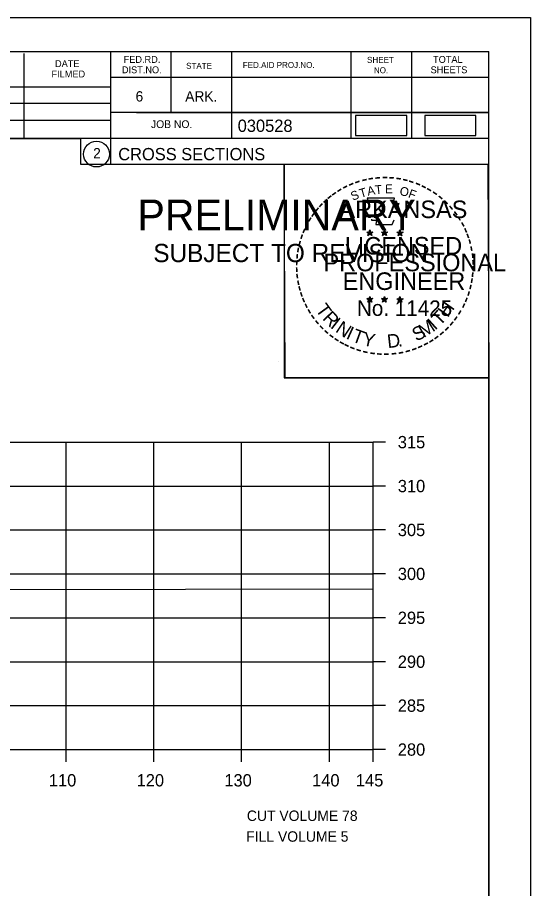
# Model space of a CAD drawing. Extents: x 1370843 to 1371177, y 380307 to 382654.
# Drawn here: x 1371118.2 to 1371176.6, y 380421.6 to 380520.8 of the extents above; entities that cross this region are included whole.
import ezdxf

# ---------------------------------------------------------------- set-up
doc = ezdxf.new("R2010")
doc.units = 0
for name, color, linetype in [('R_Axis', 7, 'Continuous'), ('R_Axis Annot', 7, 'Continuous'), ('R_Border', 7, 'Continuous'), ('R_Border Notes', 7, 'Continuous'), ('R_Border PE', 7, 'Continuous'), ('R_Border Prem', 7, 'Continuous'), ('R_Draft', 7, 'Continuous'), ('R_Exist Surface', 7, 'Continuous'), ('R_Grid', 7, 'Continuous'), ('R_No Plot', 7, 'Continuous')]:
    doc.layers.add(name, color=color, linetype=linetype)

msp = doc.modelspace()

# ---------------------------------------------------------------- linework, layer by layer
at = {"layer": 'R_Axis'}
for p, q in [((1371158.709, 380437.448), (1371158.709, 380472.448)), ((1371160.109, 380472.448), (1371158.709, 380472.448)), ((1371160.109, 380467.448), (1371158.709, 380467.448)), ((1371160.109, 380462.448), (1371158.709, 380462.448)), ((1371160.109, 380457.448), (1371158.709, 380457.448)), ((1371160.109, 380452.448), (1371158.709, 380452.448)), ((1371160.109, 380447.448), (1371158.709, 380447.448)), ((1371160.109, 380442.448), (1371158.709, 380442.448)), ((1370868.709, 380437.448), (1371158.709, 380437.448)), ((1371123.709, 380436.048), (1371123.709, 380437.448)), ((1371133.709, 380436.048), (1371133.709, 380437.448)), ((1371143.709, 380436.048), (1371143.709, 380437.448)), ((1371153.709, 380436.048), (1371153.709, 380437.448)), ((1371158.709, 380436.048), (1371158.709, 380437.448)), ((1371160.109, 380437.448), (1371158.709, 380437.448))]:
    msp.add_line(p, q, dxfattribs=at)
at = {"layer": 'R_Border'}
for p, q in [((1370855.709, 380516.908), (1371171.889, 380516.908)), ((1371118.929, 380507.028), (1371118.929, 380516.708)), ((1371128.789, 380516.908), (1371128.789, 380504.108)), ((1371135.629, 380516.908), (1371135.629, 380509.968)), ((1371142.569, 380516.908), (1371142.569, 380507.028)), ((1371156.149, 380516.908), (1371156.149, 380507.028)), ((1371163.089, 380516.908), (1371163.089, 380507.028)), ((1371171.889, 380311.448), (1371171.889, 380516.908)), ((1371171.889, 380513.968), (1371128.789, 380513.968)), ((1371171.889, 380513.988), (1371171.889, 380513.988)), ((1371089.629, 380512.888), (1371128.789, 380512.888)), ((1371089.629, 380511.028), (1371128.789, 380511.028)), ((1371171.889, 380509.968), (1371128.789, 380509.968)), ((1371131.749, 380509.968), (1371171.889, 380509.968)), ((1371089.629, 380509.088), (1371128.789, 380509.088)), ((1371171.889, 380507.028), (1371089.629, 380507.028)), ((1371128.789, 380504.108), (1371171.889, 380504.108))]:
    msp.add_line(p, q, dxfattribs=at)
msp.add_circle((1371127.176, 380505.244), 1.467, dxfattribs=at)
at = {"layer": 'R_Border PE'}
for p, q in [((1371157.974, 380496.363), (1371158.323, 380496.252)), ((1371157.974, 380496.363), (1371158.227, 380496.318)), ((1371157.974, 380496.363), (1371158.211, 380496.241)), ((1371158.107, 380495.955), (1371158.323, 380496.252)), ((1371158.107, 380495.955), (1371158.233, 380496.199)), ((1371158.107, 380495.955), (1371158.321, 380496.172)), ((1371158.323, 380496.617), (1371158.282, 380496.365)), ((1371158.536, 380495.955), (1371158.321, 380496.169)), ((1371158.323, 380496.252), (1371158.323, 380496.617)), ((1371158.323, 380496.617), (1371158.372, 380496.367)), ((1371158.67, 380496.363), (1371158.323, 380496.252)), ((1371158.536, 380495.955), (1371158.323, 380496.252)), ((1371158.67, 380496.363), (1371158.384, 380496.314)), ((1371158.536, 380495.955), (1371158.399, 380496.246)), ((1371158.67, 380496.363), (1371158.466, 380496.261)), ((1371159.644, 380496.363), (1371159.993, 380496.252)), ((1371159.644, 380496.363), (1371159.897, 380496.318)), ((1371159.644, 380496.363), (1371159.881, 380496.241)), ((1371159.777, 380495.955), (1371159.993, 380496.252)), ((1371159.777, 380495.955), (1371159.903, 380496.199)), ((1371159.777, 380495.955), (1371159.991, 380496.172)), ((1371159.993, 380496.617), (1371159.952, 380496.365)), ((1371160.206, 380495.955), (1371159.991, 380496.169)), ((1371159.993, 380496.252), (1371159.993, 380496.617)), ((1371159.993, 380496.617), (1371160.042, 380496.367)), ((1371160.34, 380496.363), (1371159.993, 380496.252)), ((1371160.206, 380495.955), (1371159.993, 380496.252)), ((1371160.34, 380496.363), (1371160.054, 380496.314)), ((1371160.206, 380495.955), (1371160.069, 380496.246)), ((1371160.34, 380496.363), (1371160.136, 380496.261)), ((1371161.408, 380496.351), (1371161.757, 380496.24)), ((1371161.408, 380496.351), (1371161.661, 380496.306)), ((1371161.408, 380496.351), (1371161.645, 380496.229)), ((1371161.541, 380495.943), (1371161.757, 380496.24)), ((1371161.541, 380495.943), (1371161.667, 380496.187)), ((1371161.541, 380495.943), (1371161.755, 380496.16)), ((1371161.757, 380496.605), (1371161.716, 380496.353)), ((1371161.97, 380495.943), (1371161.755, 380496.157)), ((1371161.757, 380496.24), (1371161.757, 380496.605)), ((1371161.757, 380496.605), (1371161.806, 380496.355)), ((1371162.104, 380496.351), (1371161.757, 380496.24)), ((1371161.97, 380495.943), (1371161.757, 380496.24)), ((1371162.104, 380496.351), (1371161.818, 380496.302)), ((1371161.97, 380495.943), (1371161.833, 380496.234)), ((1371162.104, 380496.351), (1371161.9, 380496.249)), ((1371157.97, 380488.79), (1371158.319, 380488.679)), ((1371157.97, 380488.79), (1371158.223, 380488.745)), ((1371157.97, 380488.79), (1371158.207, 380488.668)), ((1371158.319, 380489.044), (1371158.278, 380488.792)), ((1371158.319, 380488.679), (1371158.319, 380489.044)), ((1371158.319, 380489.044), (1371158.368, 380488.794)), ((1371158.666, 380488.79), (1371158.319, 380488.679)), ((1371158.666, 380488.79), (1371158.38, 380488.741)), ((1371158.666, 380488.79), (1371158.462, 380488.688)), ((1371159.639, 380488.79), (1371159.988, 380488.679)), ((1371159.639, 380488.79), (1371159.892, 380488.745)), ((1371159.639, 380488.79), (1371159.876, 380488.668)), ((1371159.988, 380489.044), (1371159.947, 380488.792)), ((1371159.988, 380488.679), (1371159.988, 380489.044)), ((1371159.988, 380489.044), (1371160.037, 380488.794)), ((1371160.335, 380488.79), (1371159.988, 380488.679)), ((1371160.335, 380488.79), (1371160.049, 380488.741)), ((1371160.335, 380488.79), (1371160.131, 380488.688)), ((1371161.406, 380488.78), (1371161.755, 380488.669)), ((1371161.406, 380488.78), (1371161.659, 380488.735)), ((1371161.406, 380488.78), (1371161.643, 380488.658)), ((1371161.755, 380489.034), (1371161.714, 380488.782)), ((1371161.755, 380488.669), (1371161.755, 380489.034)), ((1371161.755, 380489.034), (1371161.804, 380488.784)), ((1371162.102, 380488.78), (1371161.755, 380488.669)), ((1371162.102, 380488.78), (1371161.816, 380488.731)), ((1371162.102, 380488.78), (1371161.898, 380488.678)), ((1371158.103, 380488.382), (1371158.319, 380488.679)), ((1371158.103, 380488.382), (1371158.229, 380488.626)), ((1371158.103, 380488.382), (1371158.317, 380488.599)), ((1371158.532, 380488.382), (1371158.317, 380488.596)), ((1371158.532, 380488.382), (1371158.319, 380488.679)), ((1371158.532, 380488.382), (1371158.395, 380488.673)), ((1371159.772, 380488.382), (1371159.988, 380488.679)), ((1371159.772, 380488.382), (1371159.898, 380488.626)), ((1371159.772, 380488.382), (1371159.986, 380488.599)), ((1371160.201, 380488.382), (1371159.986, 380488.596)), ((1371160.201, 380488.382), (1371159.988, 380488.679)), ((1371160.201, 380488.382), (1371160.064, 380488.673)), ((1371161.539, 380488.372), (1371161.755, 380488.669)), ((1371161.539, 380488.372), (1371161.665, 380488.616)), ((1371161.539, 380488.372), (1371161.753, 380488.589)), ((1371161.968, 380488.372), (1371161.753, 380488.586)), ((1371161.968, 380488.372), (1371161.755, 380488.669)), ((1371161.968, 380488.372), (1371161.831, 380488.663))]:
    msp.add_line(p, q, dxfattribs=at)
for points in [[(1371158.015, 380500.241), (1371158.284, 380499.414)], [(1371161.526, 380499.319), (1371161.668, 380499.603), (1371160.983, 380499.579), (1371161.131, 380500.241), (1371158.015, 380500.241)], [(1371158.507, 380497.818), (1371158.507, 380497.731), (1371159.07, 380497.712), (1371159.016, 380497.239), (1371160.886, 380497.239), (1371161.087, 380497.775)], [(1371158.323, 380496.617), (1371158.536, 380495.955), (1371157.974, 380496.363), (1371158.67, 380496.363), (1371158.107, 380495.955), (1371158.323, 380496.617)], [(1371159.993, 380496.617), (1371160.206, 380495.955), (1371159.644, 380496.363), (1371160.34, 380496.363), (1371159.777, 380495.955), (1371159.993, 380496.617)], [(1371161.757, 380496.605), (1371161.97, 380495.943), (1371161.408, 380496.351), (1371162.104, 380496.351), (1371161.541, 380495.943), (1371161.757, 380496.605)], [(1371158.319, 380489.044), (1371158.532, 380488.382), (1371157.97, 380488.79), (1371158.666, 380488.79), (1371158.103, 380488.382), (1371158.319, 380489.044)], [(1371159.988, 380489.044), (1371160.201, 380488.382), (1371159.639, 380488.79), (1371160.335, 380488.79), (1371159.772, 380488.382), (1371159.988, 380489.044)], [(1371161.755, 380489.034), (1371161.968, 380488.372), (1371161.406, 380488.78), (1371162.102, 380488.78), (1371161.539, 380488.372), (1371161.755, 380489.034)]]:
    msp.add_lwpolyline(points, dxfattribs=at)
for centre, radius in [((1371158.322, 380496.251), 0.172), ((1371158.322, 380496.251), 0.145), ((1371158.322, 380496.251), 0.116), ((1371158.322, 380496.251), 0.0991), ((1371158.322, 380496.251), 0.0747), ((1371158.322, 380496.251), 0.0495), ((1371158.322, 380496.251), 0.0296), ((1371159.992, 380496.251), 0.172), ((1371159.992, 380496.251), 0.145), ((1371159.992, 380496.251), 0.116), ((1371159.992, 380496.251), 0.0991), ((1371159.992, 380496.251), 0.0747), ((1371159.992, 380496.251), 0.0495), ((1371159.992, 380496.251), 0.0296), ((1371161.756, 380496.239), 0.172), ((1371161.756, 380496.239), 0.145), ((1371161.756, 380496.239), 0.116), ((1371161.756, 380496.239), 0.0991), ((1371161.756, 380496.239), 0.0747), ((1371161.756, 380496.239), 0.0495), ((1371161.756, 380496.239), 0.0296), ((1371158.318, 380488.678), 0.172), ((1371158.318, 380488.678), 0.145), ((1371158.318, 380488.678), 0.116), ((1371158.318, 380488.678), 0.0991), ((1371158.318, 380488.678), 0.0747), ((1371158.318, 380488.678), 0.0495), ((1371159.987, 380488.678), 0.172), ((1371159.987, 380488.678), 0.145), ((1371159.987, 380488.678), 0.116), ((1371159.987, 380488.678), 0.0991), ((1371159.987, 380488.678), 0.0747), ((1371159.987, 380488.678), 0.0495), ((1371161.754, 380488.668), 0.172), ((1371161.754, 380488.668), 0.145), ((1371161.754, 380488.668), 0.116), ((1371161.754, 380488.668), 0.0991), ((1371161.754, 380488.668), 0.0747), ((1371158.318, 380488.678), 0.0296), ((1371159.987, 380488.678), 0.0296), ((1371161.754, 380488.668), 0.0495), ((1371161.754, 380488.668), 0.0296)]:
    msp.add_circle(centre, radius, dxfattribs=at)
at = {"layer": 'R_Draft'}
for points in [[(1371156.702, 380507.343), (1371162.536, 380507.343), (1371162.536, 380509.653), (1371156.702, 380509.653)], [(1371164.572, 380507.343), (1371170.406, 380507.343), (1371170.406, 380509.653), (1371164.572, 380509.653)]]:
    msp.add_lwpolyline(points, close=True, dxfattribs=at)
at = {"layer": 'R_Exist Surface'}
msp.add_line((1371109.054, 380455.675), (1371158.709, 380455.742), dxfattribs=at)
at = {"layer": 'R_Grid'}
for p, q in [((1370868.709, 380472.448), (1371158.709, 380472.448)), ((1371123.709, 380437.448), (1371123.709, 380472.448)), ((1371133.709, 380437.448), (1371133.709, 380472.448)), ((1371143.709, 380437.448), (1371143.709, 380472.448)), ((1371153.709, 380437.448), (1371153.709, 380472.448)), ((1371158.709, 380437.448), (1371158.709, 380472.448)), ((1370868.709, 380467.448), (1371158.709, 380467.448)), ((1370868.709, 380462.448), (1371158.709, 380462.448)), ((1370868.709, 380457.448), (1371158.709, 380457.448)), ((1370868.709, 380452.448), (1371158.709, 380452.448)), ((1370868.709, 380447.448), (1371158.709, 380447.448)), ((1370868.709, 380442.448), (1371158.709, 380442.448)), ((1370868.709, 380437.448), (1371158.709, 380437.448))]:
    msp.add_line(p, q, dxfattribs=at)
at = {"layer": 'R_No Plot'}
for p, q in [((1370843.308, 380520.803), (1371176.642, 380520.803)), ((1371147.923, 380481.653), (1371147.923, 380481.653))]:
    msp.add_line(p, q, dxfattribs=at)
for points in [[(1370843.302, 380520.803), (1371176.642, 380520.803), (1371176.642, 380307.465), (1370843.302, 380307.465)], [(1371089.629, 380516.908), (1371089.629, 380507.028), (1371125.361, 380507.028), (1371125.361, 380504.108), (1371148.561, 380504.108), (1371148.561, 380479.776), (1371171.889, 380479.776), (1371171.889, 380311.448), (1370855.709, 380311.448), (1370855.709, 380516.908)], [(1371148.561, 380504.108), (1371171.768, 380504.108), (1371171.889, 380479.776), (1371148.681, 380479.776)]]:
    msp.add_lwpolyline(points, close=True, dxfattribs=at)

# ---------------------------------------------------------------- texts
at = {"layer": 'R_Axis Annot'}
for s, p in [('315', (1371161.509, 380471.748)), ('310', (1371161.509, 380466.748)), ('305', (1371161.509, 380461.748)), ('300', (1371161.509, 380456.748)), ('295', (1371161.509, 380451.748)), ('290', (1371161.509, 380446.748)), ('285', (1371161.509, 380441.748)), ('280', (1371161.509, 380436.748)), ('110', (1371121.748, 380433.248)), ('120', (1371131.748, 380433.248)), ('130', (1371141.748, 380433.248)), ('140', (1371151.748, 380433.248)), ('145', (1371156.735, 380433.248))]:
    msp.add_text(s, height=1.4, dxfattribs=at).set_placement(p)
at = {"layer": 'R_Border'}
for s, height, p in [('DATE', 0.7819, (1371122.449, 380515.148)), ('FED.RD.', 0.7819, (1371130.269, 380515.628)), ('STATE', 0.684, (1371137.389, 380514.948)), ('FED.AID PROJ.NO.', 0.684, (1371143.849, 380515.048)), ('SHEET', 0.684, (1371158.009, 380515.628)), ('TOTAL', 0.7819, (1371165.529, 380515.628)), ('FILMED', 0.7819, (1371122.049, 380513.968)), ('DIST.NO.', 0.7819, (1371130.069, 380514.448)), ('NO.', 0.684, (1371158.789, 380514.448)), ('SHEETS', 0.7819, (1371165.249, 380514.448)), ('6', 1.172, (1371131.629, 380511.228)), ('ARK.', 1.1723, (1371137.289, 380511.228)), ('JOB NO.', 0.8792, (1371133.389, 380508.208)), ('030528', 1.4, (1371143.265, 380507.768)), ('2', 1.172, (1371126.793, 380504.757)), ('CROSS SECTIONS', 1.4, (1371129.653, 380504.538))]:
    msp.add_text(s, height=height, rotation=360, dxfattribs=at).set_placement(p)
at = {"layer": 'R_Border Notes'}
for s, p in [('CUT VOLUME 78', (1371144.31, 380429.317)), ('FILL VOLUME 5', (1371144.235, 380426.954))]:
    msp.add_text(s, height=1.18747, dxfattribs=at).set_placement(p)
at = {"layer": 'R_Border PE'}
for s, height, rotation, p in [('-', 1.6, 5.89682, (1371158.92, 380501.881)), ('-', 1.6, 0.18623, (1371159.692, 380501.953)), ('-', 1.6, 357.74304, (1371160.415, 380501.94)), ('-', 1.6, 28.79182, (1371155.496, 380500.782)), ('-', 1.6, 24.30721, (1371156.129, 380501.099)), ('-', 1.6, 19.17608, (1371156.763, 380501.368)), ('-', 1.6, 13.63015, (1371157.513, 380501.609)), ('-', 1.6, 10.21935, (1371158.191, 380501.771)), ('T', 1, 6.02276, (1371158.959, 380500.667)), ('E', 1, 0.83234, (1371160.064, 380500.777)), ('-', 1.6, 352.16172, (1371161.159, 380501.884)), ('-', 1.6, 347.20489, (1371161.878, 380501.77)), ('-', 1.6, 342.3362, (1371162.513, 380501.615)), ('-', 1.6, 337.85509, (1371163.248, 380501.392)), ('-', 1.6, 334.12109, (1371163.879, 380501.121)), ('-', 1.6, 36.23174, (1371154.321, 380500.017)), ('-', 1.6, 34.06357, (1371154.899, 380500.412)), ('S', 1, 21.59401, (1371156.37, 380499.919)), ('T', 1, 16.4036, (1371157.284, 380500.25)), ('A', 1, 11.21318, (1371158.11, 380500.501)), ('O', 1, 350.4515, (1371161.668, 380500.567)), ('F', 1, 340.07066, (1371162.622, 380500.339)), ('-', 1.6, 329.64089, (1371164.458, 380500.838)), ('-', 1.6, 325.86266, (1371165.101, 380500.477)), ('-', 1.6, 48.42305, (1371152.964, 380498.744)), ('-', 1.6, 42.96224, (1371153.412, 380499.222)), ('-', 1.6, 38.95066, (1371153.845, 380499.639)), ('ARKANSAS', 2, 360, (1371154.868, 380497.953)), ('-', 1.6, 320.52971, (1371165.711, 380500.051)), ('-', 1.6, 315.57859, (1371166.31, 380499.563)), ('-', 1.6, 50.61417, (1371152.561, 380498.258)), ('-', 1.6, 309.87973, (1371166.879, 380499.013)), ('-', 1.6, 306.65218, (1371167.404, 380498.411)), ('-', 1.6, 58.07063, (1371151.823, 380497.164)), ('-', 1.6, 54.23247, (1371152.148, 380497.691)), ('-', 1.4, 303.67529, (1371167.89, 380497.843)), ('-', 1.6, 67.77427, (1371151.251, 380495.939)), ('-', 1.6, 62.87135, (1371151.51, 380496.55)), ('-', 1.6, 299.66835, (1371168.209, 380497.236)), ('-', 1.6, 294.66279, (1371168.533, 380496.624)), ('-', 1.6, 72.39447, (1371151.032, 380495.309)), ('LICENSED', 2, 360, (1371155.465, 380493.804)), ('DWB', 0.01, 360, (1371158.31, 380496.247)), ('DWB', 0.01, 360, (1371159.98, 380496.247)), ('DWB', 0.01, 360, (1371161.744, 380496.236)), ('-', 1.6, 290.57283, (1371168.79, 380496.047)), ('-', 1.6, 75.46096, (1371150.835, 380494.595)), ('-', 1.6, 285.12326, (1371169.024, 380495.467)), ('-', 1.6, 280.54934, (1371169.224, 380494.725)), ('-', 1.6, 85.18634, (1371150.627, 380493.191)), ('-', 1.6, 81.20126, (1371150.703, 380493.882)), ('PROFESSIONAL', 2, 360, (1371153.042, 380491.9)), ('-', 1.6, 276.59616, (1371169.386, 380493.957)), ('-', 1.6, 89.06224, (1371150.602, 380492.49)), ('-', 1.6, 274.33011, (1371169.446, 380493.235)), ('-', 1.6, 94.19588, (1371150.637, 380491.765)), ('ENGINEER', 2, 360, (1371155.229, 380489.775)), ('-', 1.6, 263.5172, (1371169.461, 380491.937)), ('-', 1.6, 269.94067, (1371169.48, 380492.603)), ('-', 1.6, 98.94793, (1371150.709, 380491.098)), ('-', 1.6, 101.71495, (1371150.844, 380490.365)), ('-', 1.6, 260.99529, (1371169.39, 380491.283)), ('-', 1.6, 105.45785, (1371151.006, 380489.77)), ('-', 1.6, 255.7626, (1371169.28, 380490.605)), ('-', 1.6, 109.08742, (1371151.221, 380489.139)), ('-', 1.6, 114.06432, (1371151.475, 380488.543)), ('-', 1.6, 247.88866, (1371168.876, 380489.212)), ('-', 1.6, 252.86809, (1371169.099, 380489.885)), ('-', 1.6, 115.72885, (1371151.78, 380487.925)), ('T', 1.54, 306.04056, (1371152.078, 380487.517)), ('No. 11425', 1.757, 360, (1371156.856, 380486.824)), ('DWB', 0.01, 360, (1371158.306, 380488.674)), ('DWB', 0.01, 360, (1371159.975, 380488.674)), ('DWB', 0.01, 360, (1371161.742, 380488.664)), ('H', 1.54, 54.60883, (1371167.199, 380486.553)), ('-', 1.6, 244.61971, (1371168.614, 380488.583)), ('-', 1.6, 120.44712, (1371152.137, 380487.339)), ('-', 1.6, 125.89344, (1371152.54, 380486.778)), ('R', 1.54, 314.00497, (1371152.841, 380486.47)), ('T', 1.54, 46.64442, (1371166.309, 380485.61)), ('-', 1.6, 233.84524, (1371167.818, 380487.178)), ('-', 1.6, 239.07125, (1371168.22, 380487.831)), ('-', 1.6, 130.71812, (1371153.002, 380486.226)), ('-', 1.6, 134.22381, (1371153.519, 380485.681)), ('I', 1.54, 321.96938, (1371153.741, 380485.538)), ('N', 1.54, 326.50021, (1371154.309, 380485.066)), ('M', 1.54, 32.65632, (1371164.463, 380484.285)), ('I', 1.54, 42.11359, (1371165.747, 380485.132)), ('-', 1.6, 231.25377, (1371167.388, 380486.612)), ('-', 1.6, 138.93382, (1371154.044, 380485.217)), ('I', 1.54, 335.36034, (1371155.517, 380484.28)), ('T', 1.54, 339.89117, (1371156.178, 380483.953)), ('Y', 1.54, 347.85558, (1371157.395, 380483.507)), ('D', 1.54, 6.39691, (1371160.38, 380483.149)), ('S', 1.54, 26.9312, (1371163.624, 380483.879)), ('-', 1.6, 221.08509, (1371166.387, 380485.539)), ('-', 1.6, 225.76533, (1371166.909, 380486.048)), ('-', 1.6, 144.64634, (1371154.6, 380484.811)), ('-', 1.6, 148.08978, (1371155.161, 380484.44)), ('-', 1.6, 151.57039, (1371155.74, 380484.115)), ('-', 1.6, 207.35684, (1371164.746, 380484.334)), ('-', 1.6, 212.24909, (1371165.304, 380484.68)), ('-', 1.6, 215.73633, (1371165.838, 380485.067)), ('-', 1.6, 154.60019, (1371156.262, 380483.868)), ('-', 1.6, 158.56121, (1371156.886, 380483.614)), ('-', 1.6, 162.79826, (1371157.573, 380483.401)), ('-', 1.6, 167.55551, (1371158.288, 380483.237)), ('.', 1.54, 13.76417, (1371161.572, 380483.276)), ('-', 1.6, 195.47429, (1371162.826, 380483.5)), ('-', 1.6, 200.71842, (1371163.503, 380483.742)), ('-', 1.6, 204.25161, (1371164.122, 380484.015)), ('-', 1.6, 173.11546, (1371159.06, 380483.127)), ('-', 1.6, 176.51827, (1371159.808, 380483.074)), ('-', 1.6, 181.59176, (1371160.552, 380483.093)), ('-', 1.6, 185.81666, (1371161.361, 380483.169)), ('-', 1.6, 191.28576, (1371162.097, 380483.301))]:
    msp.add_text(s, height=height, rotation=rotation, dxfattribs=at).set_placement(p)
at = {"layer": 'R_Border Prem'}
for s, height, p in [('PRELIMINARY', 3.5, (1371131.84, 380496.571)), ('DWB', 0.01, (1371132.587, 380498.42)), ('SUBJECT TO REVISION', 2.07511, (1371133.649, 380492.942))]:
    msp.add_text(s, height=height, rotation=360, dxfattribs=at).set_placement(p)

doc.saveas('drawing.dxf')
